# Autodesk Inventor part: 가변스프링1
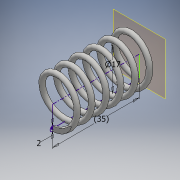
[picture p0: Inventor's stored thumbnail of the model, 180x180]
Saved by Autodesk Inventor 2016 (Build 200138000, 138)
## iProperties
Created: 2021-02
Part Number: 가변스프링1
Material: 일반
Document SubType Name: Modeling
Designer: Windows7
Density: 1 g/cm^3
Appearance: 기본값
Mass: 0.990408 g
Surface Area: 20.0926 cm^2
Volume: 0.990408 cm^3
Author: Windows7
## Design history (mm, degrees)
sketch "스케치1"
  geometry: L1 (0, 0)-(26.33, 0); L2 (26.33, 0)-(26.33, -8.5); L3 (26.33, -8.5)-(0, -8.5); L4 (0, -8.5)-(0, 0); C1 r 1 at (0, -8.5)
  constraints: 8 end point, 2 parallel, 1 centre point, 1 coincident, 1 horizontal, 1 perpendicular
  dimensions: "d0" = 2 diameter of C1; "d1" = 17 diameter of L3 L1; "d2" = 26.33013 distance of L2.end L3.end (derived)
feature "코일1" pitch "d3" = 10; turns "d5" = 6; dims "d4" = 26.33013 (= d2), "d6" = 0, angle "d7" = 90 deg, angle "d8" = 90 deg, "d9" = 0, "d10" = 0
feature "분할1"
node "작업 평면1"
feature "분할2"
node "솔리드1"
other parameters: "d11" = 90 deg
